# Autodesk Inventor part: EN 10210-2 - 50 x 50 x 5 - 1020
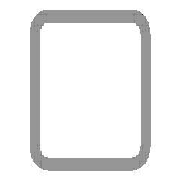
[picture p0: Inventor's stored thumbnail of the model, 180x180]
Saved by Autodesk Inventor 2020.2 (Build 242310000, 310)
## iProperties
IsCustomPart: 1
_CCFamilyMember: 16
_CCFamilyDisplayName: DIN EN 10210-2 (USAS B17.1 quadratisch) - Rohrleitung — In Klammern angegebene Größen wurden aufgehoben
_FrameMemberDoc: Frame Member File
_Version: 15.0.0
_GetPNFromCC: 1
Created: 2019-10
Part Number: EN 10210-2 - 50 x 50 x 5 - 1020
Material: Stahl, weich
Description: Rohrleitung
Document SubType Name: Modeling
Standard: DIN
Designer: lutzd
Standard Revision: 2006-07
Standards Organization: DIN
Language: de-DE
Size Designation: 50 x 50 x 5
Categories: <MemberInstance><Categories><Category DisplayName="Profile" InternalName="089c4875-fa83-4c05-b084-43b9cc11f5ed" Mnemonic="GRDR"><CategoryParameter DisplayName="
Stock Number: 50 x 50 x 5
Mass: 6991.51 g
Surface Area: 3470.57 cm^2
Volume: 890.638 cm^3
Density: 7.85 g/cm^3
Appearance: Semi-Polished(8)
G_L: 1020,000 mm
G_W: 50,000 mm
G_H: 50,000 mm
Dimensions: 50x50x1020 mm
Mass: 6,992 kg
DocNumber: ADSK-014285
Folder: .
+7B86A794-3F52-4C88-837F-4F538E35C7CF+SCHNITTDETAIL1: Schnittwinkel 90,00 grd
+2D4B6A12-F381-47E5-BE40-4113F7B76D9F+SCHNITTDETAIL2: Schnittwinkel 90,00 grd
VLT_Material: Stahl, weich
Title: Profil-Bauteil
Author: lutzd
Revision Number: -
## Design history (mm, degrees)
node "Startebene"
node "Endebene"
sketch "Skizze"
  geometry: L1 (-25, -17.5)-(-25, 17.5); L2 (-17.5, 25)-(17.5, 25); L3 (25, 17.5)-(25, -17.5); L4 (17.5, -25)-(-17.5, -25); L5 (-15, 20)-(15, 20); L6 (20, 15)-(20, -15); L7 (15, -20)-(-15, -20); L8 (-20, -15)-(-20, 15); L9 (0, 37.175)-(0, -37.175) reference; L10 (-37.175, 0)-(37.175, 0) reference; A1 r 7.5 centre (-17.5, -17.5) between (-25, -17.5) and (-17.5, -25); A2 r 7.5 centre (-17.5, 17.5) between (-17.5, 25) and (-25, 17.5); A3 r 7.5 centre (17.5, 17.5) between (25, 17.5) and (17.5, 25); A4 r 7.5 centre (17.5, -17.5) between (17.5, -25) and (25, -17.5); A5 r 5 centre (-15, -15) between (-20, -15) and (-15, -20); A6 r 5 centre (-15, 15) between (-15, 20) and (-20, 15); A7 r 5 centre (15, 15) between (20, 15) and (15, 20); A8 r 5 centre (15, -15) between (15, -20) and (20, -15)
  constraints: 16 end point, 16 point on circle, 16 tangent, 8 centre point, 6 equal radius, 4 parallel, 2 perpendicular, 2 other
  dimensions: "d7" = 7.5 radius of A1 (= G_IR); "d10" = 50 distance between parallel lines of L2 L4 (= G_H); "d11" = 50 distance between parallel lines of L1 L3 (= G_W); "d12" = 5 distance between parallel lines of L3 L6 (= G_T); "d15" = 25 distance between parallel lines of L2 L10 (= 0.5 x d10); "d16" = 25 distance between parallel lines of L9 L3 (= 0.5 x d11); "d19" = 5 radius of A5 (= G_T); "d20" = 5 distance between parallel lines of L4 L7 (= G_T)
extrude "Körper" new body sketch "Skizze" stored distance "d3" = 1020 (= G_L); taper "d4" = 0 deg
node "Driven Length"
  sketch "Sketch3"
    geometry: L1 (0, 0)-(10, 0) reference
    constraints: 2 end point, 1 horizontal
  workplane "Work Plane3"
  sketch "Sketch4"
    geometry: L1 (-2, 25)-(12, 25) reference; L2 (-2, 1045)-(12, 1045) reference
    dimensions: "d18" = 1020 distance between parallel lines of L1 L2 (derived)
workplane "Arbeitsebene4"
feature "Trennen1"
workplane "Arbeitsebene5"
feature "Trennen2"
body "Solid1"
other parameters: "G_W" = 50 [user parameter; used in 1 equation term], "G_H" = 50 [user parameter; used in 1 equation term], "G_T" = 5 [user parameter; used in 3 equation terms], "G_IR" = 7.5 [user parameter; used in 1 equation term], "G_L" = 1020 (= d18) [user parameter; used in 1 equation term], "G_OFFSET_START" = -25 [user parameter; used in 1 equation term], "d13" = 25 (= -G_OFFSET_START), "d14" = 1045 (= G_OFFSET_END + B_L), "B_L" = 1095 [user parameter; used in 1 equation term], "d17" = 90 deg
